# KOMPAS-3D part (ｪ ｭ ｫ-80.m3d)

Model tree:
1. Эскиз:1
2. Операция выдавливания:1
     Расстояние 1 = 1
3. Эскиз:2
4. Операция выдавливания:2
     Расстояние 1 = 2
5. Эскиз:3
6. Вырезать элемент выдавливания:1
     Расстояние 1 = 200
7. Эскиз:4
8. Операция выдавливания:3
     Расстояние 1 = 5
9. Эскиз:5
10. Операция выдавливания:4
     Расстояние 1 = 1
11. Эскиз:6
12. Операция выдавливания:5
     Расстояние 1 = 9
13. Эскиз:7
14. Операция выдавливания:6
     Расстояние 1 = 9; Расстояние 2 = 200
15. Эскиз:8
16. Вырезать элемент выдавливания:2
     Расстояние 1 = 10
